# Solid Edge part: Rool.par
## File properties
Author: Türk
Template: Iso Part.par
Last saved by: Türk
Revision: 8
Application: Solid Edge
Accuracy: 0,990
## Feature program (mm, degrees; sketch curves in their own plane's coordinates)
pattern "PatternOccurrence_1"  XOffset = 120 deg
pattern "PatternOccurrence_2"  XOffset = 24 deg
pattern "PatternOccurrence_3"  XOffset = 24 deg
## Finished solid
Body 1: sheet body, 3 faces, 26 edges, 26 vertices.
  Faces by surface: plane 3
  Edges by curve: line 26
Body 2: solid body, 130 faces, 253 edges, 120 vertices.
  Faces by surface: plane 76, cylinder 53, cone 1
  Edges by curve: line 120, circle 115, ellipse 18
Bounding box of the edges (mm): 370.000 x 230.000 x 370.000, from (-185, -180, -185) to (185, 50, 185).
Cylindrical faces by radius (mm): R2 x12, R5 x30, R30 x2, R35 x1, R40 x1, R147.2985 x3, R165 x3, R185 x1
Conical faces (half-angle, radius in mm at the cone's reference point): 45 deg R35 x1
Planar faces by outward normal: +y 19, -y 24, oblique 33
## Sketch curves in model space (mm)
line (-14.2613, -125, 35) -> (-9.7316, -172.395, 164.7128)
line (0, -125, 35) -> (-14.2613, -125, 35)
line (14.2613, -125, 35) -> (0, -125, 35)
line (14.2613, -125, 35) -> (9.7316, -172.395, 164.7128)
ellipse centre (0, -112.2115, 0) radii 175.6693, 165 from (9.7316, -172.395, 164.7128) through (4.8679, -172.4738, 164.9282) to (0, -172.5, 165)
ellipse centre (0, -112.2115, 0) radii 175.6693, 165 from (0, -172.5, 165) through (-4.8679, -172.4738, 164.9282) to (-9.7316, -172.395, 164.7128)
line (3.0274, -169.2609, 156.1352) -> (6.9438, -128.2828, 43.9846)
arc centre (4.9449, -128.2603, 43.923) radius 2 from (6.9438, -128.2828, 43.9846) through (6.3401, -127.7686, 42.5771) to (4.9449, -127.5739, 42.0445)
line (4.9449, -127.5739, 42.0445) -> (-4.9449, -127.5739, 42.0445)
arc centre (-4.9449, -128.2603, 43.923) radius 2 from (-4.9449, -127.5739, 42.0445) through (-6.4227, -127.7979, 42.6573) to (-6.9438, -128.2828, 43.9846)
line (-6.9438, -128.2828, 43.9846) -> (-3.0274, -169.2609, 156.1351)
arc centre (-1.0285, -169.2384, 156.0736) radius 2 from (-3.0274, -169.2609, 156.1351) through (-2.4244, -169.73, 157.4188) to (-1.0427, -169.9248, 157.952)
arc centre (0.0014, -119.3742, 19.6032) radius 147.2985 from (-1.0427, -169.9248, 157.952) through (0, -169.9261, 157.9555) to (1.0426, -169.9248, 157.9521)
arc centre (1.0285, -169.2384, 156.0736) radius 2 from (1.0426, -169.9248, 157.9521) through (2.4244, -169.73, 157.4189) to (3.0274, -169.2609, 156.1352)
circle centre (0, -170, 0) radius 175
line (0, -130, 0) -> (0, -170, 0)
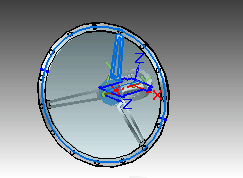
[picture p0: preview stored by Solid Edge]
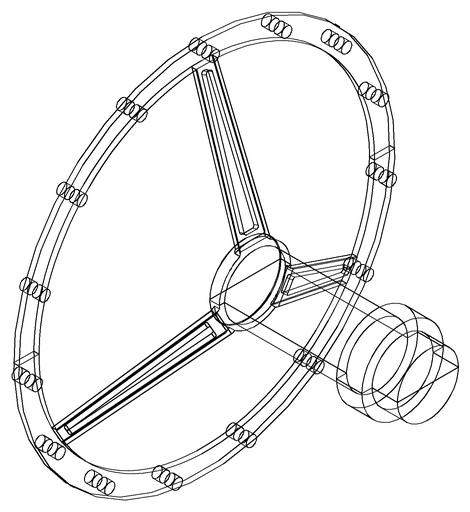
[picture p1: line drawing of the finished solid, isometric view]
